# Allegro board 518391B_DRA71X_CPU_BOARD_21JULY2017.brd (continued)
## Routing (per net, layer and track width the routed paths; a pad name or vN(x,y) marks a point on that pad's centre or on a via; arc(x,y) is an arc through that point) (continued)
GND_EARTH: length 19.9
  TOP w0.508: J7.6 J7.8 J7.9 J7.7
VBAT: length 72.1
  TOP w0.635: J4.1 9.83,141.73 ; J4.1 6.68,141.73 ; J4.1 8.25,140.16 ; J4.1 8.25,143.31 ; J4.2 8.25,138.23 ; J4.2 9.83,136.65 ; J4.2 8.25,135.08 ; J4.2 6.68,136.65
  LY3 w0.508: 6.63,141.73 J4.1 ; J4.1 8.25,140.11 ; J4.1 9.88,141.73 ; J4.1 8.25,143.36 ; 6.63,136.65 J4.2 ; J4.2 8.25,135.03 ; J4.2 8.25,138.28 ; J4.2 9.88,136.65
  LY3 w0.635: 12,158.95 J22.1 ; J22.1 13.19,161.16 ; J22.1 10.81,161.16 ; J22.1 12,163.37
  LY4 w0.508: 8.25,140.11 J4.1 ; J4.1 9.88,141.73 ; J4.1 8.25,143.36 ; J4.1 6.63,141.73 ; J4.2 9.88,136.65 ; J4.2 8.25,135.03 ; J4.2 6.63,136.65 ; J4.2 8.25,138.28
  LY4 w0.635: J22.1 13.19,161.16 ; J22.1 10.81,161.16 ; J22.1 12,158.95 ; J22.1 12,163.37
  BOTTOM w0.254: v2(12.57,142.37) 14.99,139.95 22.73,139.95 23.62,140.84 U74.8 29.08,140.84 29.29,141.05 29.29,141.54 28.98,141.84 U74.10
VBAT_A: length 25.2
  TOP w0.406: C117.2 35.31,76.83 34.73,77.41 U28.3
  TOP w0.508: 44.45,139.78 TP5.1 ; TP5.1 44.45,141.15 ; TP5.1 43.76,140.46 ; TP5.1 45.14,140.46 ; L4.2 41.64,136.52 ; L4.2 38.37,136.52 ; L4.2 40,138.16
  LY3 w0.635: C65.1 36.32,113.46 ; C65.1 37.64,112.14 ; C65.1 35,112.14 ; C65.1 36.32,110.82 ; 43.76,140.46 TP5.1 ; TP5.1 44.45,139.78 ; TP5.1 45.14,140.46 ; TP5.1 44.45,141.15 ; L4.2 40,138.16 ; L4.2 41.64,136.52 ; L4.2 38.37,136.52 ; L4.2 40,134.89
  vias: v2(25.15,93.6) v2(25.15,92.71) v2(25.15,84.96) v2(25.15,84.07) v2(25.15,76.71) v2(25.15,75.82) v2(26.03,93.6) v2(26.03,92.71) v2(26.03,84.96) v2(26.03,84.07) v2(26.03,76.71) v2(26.03,75.82) v2(30.23,77.34) v2(30.23,76.45) v2(31.11,77.34) v2(31.11,76.45) v2(35.94,141.48) v2(35.94,140.46) v2(35.94,139.45) v2(35.94,138.43) v2(37.08,141.48) v2(38.23,141.48) v2(39.37,141.48) v2(40.51,141.48) v2(41.66,141.48) v2(42.8,141.48)
VBAT_F: length 5
  TOP w0.305: R45.1 44.7,111 44.15,110.44 D9.2 ; 42.87,108.71 TP15.1 ; TP15.1 43.56,109.4 ; TP15.1 43.56,108.03 ; TP15.1 44.25,108.71
  vias: v2(43.69,135) v2(43.69,134.11) v2(43.69,133.22) v2(43.69,132.33) v2(47.12,132.33) v2(48.01,132.33) v2(48.89,132.33) v2(49.78,132.33)
VBAT_PM: length 19.1
  TOP w0.508: 16.01,131.49 U16.4 17.21,131 ; C24.1 16.76,143.12 ; C24.1 16.01,142.24 ; C24.1 16.76,141.36
  BOTTOM w0.254: U74.9 23.23,141.34 22.35,140.46 16.38,140.46 v2(14.48,142.37)
  vias: v2(12.7,148.59) v2(12.7,147.7) v2(12.7,146.81) v2(12.7,145.92) v2(12.7,145.03) v2(13.59,149.1) v2(13.59,144.53) v2(14.61,149.1) v2(14.61,144.53) v2(15.62,149.1) v2(15.62,144.53)
VBAT_SYS: length 305.4
  TOP w0.203: U18.15 v2(79.62,127.88)
  TOP w0.305: v2(79.76,130.05) 80.26,130.05 80.7,129.62 C29.1 80.7,129.46 80.26,129.03 v2(79.76,129.03)
  TOP w0.635: 73.41,137.87 C23.1 ; C23.1 72.08,139.19 ; C23.1 74.73,139.19 ; C23.1 73.41,140.51 ; C2.1 50.16,158.29 ; C2.1 50.16,155.65 ; C2.1 48.84,156.97 ; C2.1 51.49,156.97 ; 67.94,155.65 C3.1 ; C3.1 66.62,156.97 ; C3.1 67.94,158.29 ; C3.1 69.27,156.97 ; 32.38,155.65 C1.1 ; C1.1 32.38,158.29 ; C1.1 33.71,156.97 ; C1.1 31.06,156.97 ; TP1.1 23.55,160.27 ; TP1.1 22.86,160.96 ; TP1.1 22.86,159.59 ; TP1.1 22.17,160.27
  LY4 w0.305: v2(79.76,129.03) 79.62,128.9 v2(79.62,127.88)
  LY4 w0.508: v2(108.33,21.72) 106.81,23.24 89.66,23.24 89.41,23.49 78.87,23.49 77.98,22.61 52.7,22.61 50.67,24.64 48.89,24.64 48.41,25.12 43.28,25.12 40.13,21.97 37.46,21.97 36.19,23.24 26.03,23.24 24.26,25.02 24.26,29.84 19.28,34.82 19.28,54.33 20.45,55.5 20.45,60.83 19.56,61.72 19.56,93.22 22.48,96.14 22.48,102.62 35.05,115.19 68.07,115.19 v2(69.85,116.97) 72.01,119.13 v2(72.01,122.3) 72.26,122.55 v2(72.26,124.08)
  BOTTOM w0.508: v2(72.01,122.3) 72.01,122.17 71.75,121.92 C552.1 71.75,120.01 72.01,119.76 ; 69.85,115.57 v2(69.85,116.97) ; R218.2 72.39,124.21 v2(72.26,124.08)
  BOTTOM w0.635: C1.1 34.54,156.97 ; C1.1 30.23,156.97 ; C1.1 32.38,159.13 ; C1.1 32.38,154.81 ; C2.1 52.32,156.97 ; C2.1 50.16,154.81 ; C2.1 50.16,159.13 ; C2.1 48.01,156.97 ; C23.1 73.41,141.35 ; C23.1 75.57,139.19 ; C23.1 71.25,139.19 ; C23.1 73.41,137.03 ; C3.1 70.1,156.97 ; C3.1 67.94,159.13 ; C3.1 65.79,156.97 ; C3.1 67.94,154.81 ; TP1.1 22.86,160.96 ; TP1.1 22.17,160.27 ; TP1.1 22.86,159.59 ; TP1.1 23.55,160.27
  vias: v2(17.91,160.15) v2(18.03,156.34) v2(18.8,160.15) v2(19.56,156.34) v2(19.69,160.15) v2(20.57,160.15) v2(20.95,156.34) v2(22.35,157.73) v2(86.61,128.4) v2(86.61,127.51) v2(87.38,128.4) v2(87.38,127.51) v2(88.14,128.4) v2(88.14,127.51)
VBUS1_5V0: length 3.2
  TOP w0.305: v2(128.65,154.31) R1.1
  BOTTOM w0.305: J1.1 136.01,160.52 ; J1.1 135.2,161.33 ; J1.1 134.39,160.52
  vias: v2(123.19,156.97) v2(123.19,156.08) v2(123.57,155.07) v2(123.57,154.05) v2(123.57,152.78) v2(123.57,151.64)
VBUS2_5V0: length 6.8
  TOP w0.305: 157.07,160.52 J2.1 ; J2.1 157.81,159.78 ; J2.1 157.81,161.25 ; J2.1 158.54,160.52
  BOTTOM w0.305: R194.1 155.96,154.31 v2(156.08,154.18)
VCC_APL: length 13.7
  LY3 w0.305: v2(92.08,161.93) 89.92,161.93 87.5,164.34 87.5,165.35 J3.5
  BOTTOM w0.254: J3.5 86.35,166.51 U1.8
  BOTTOM w0.305: v2(92.08,161.93) 92.08,162.81 93.22,162.81
VCC_LM5141: length 7.7
  TOP w0.305: D5.2 87.3,125.27 86.31,124.28 C45.1 84.12,124.28 83.19,125.22 U18.10
VCC_LM5175: length 24.1
  TOP w0.203: v2(47.62,110.49) 47.62,110.24 R48.2
  TOP w0.305: D6.2 52.25,123.62 v2(52.2,123.57) ; D8.2 49.61,123.57 C42.1 v2(52.2,123.57) ; v2(52.2,123.57) 51.98,123.36 U19.23
  BOTTOM w0.305: v2(52.2,123.57) 52.2,120.52 50.29,118.62 50.29,113.92 47.62,111.25 v2(47.62,110.49)
VDD33_DSU921: length 7.2
  TOP w0.305: U30.22 v2(145.01,68.04) 145.92,68.96 145.92,70.23 C122.1 L17.1
  BOTTOM w0.305: v2(145.01,68.04) 144.78,67.82 C429.1
VDD_1P1_CSI: length 3.4
  TOP w0.305: U33.20 147.84,51.32 v2(147.83,51.31)
  BOTTOM w0.305: v2(147.83,51.31) 148.08,51.56 C479.1 148.59,51.05 148.84,50.8 C485.2
VDD_1P1_D: length 4.3
  TOP w0.305: C142.1 C134.2 154.31,57.4 154.47,57.24 154.47,56.46 154.15,56.14 U33.3
VDD_1P1_FPD: length 4.2
  TOP w0.305: C171.1 C172.2 153.67,47.37 154.15,47.85 U33.34
VDD_1P8: length 5.6
  TOP w0.305: v2(155.18,47.47) 155.15,47.5 U33.36 ; C135.2 v2(157.23,57.28) ; L19.1 v2(159,57.28) ; v2(156.97,53.47) 156.82,53.32 U33.45
  BOTTOM w0.305: v2(155.18,47.47) 154.94,47.71 C486.1 ; v2(156.97,53.47) C471.1
VDD_1P8_CSI: length 5.3
  TOP w0.305: U33.17 147.97,52.82 v2(147.7,53.09)
  BOTTOM w0.305: L59.1 C468.2 148.59,53.72 C472.1 148.58,52.82 147.97,52.82 v2(147.7,53.09)
VDD_1P8_FPD: length 6.6
  TOP w0.305: v2(152.64,47.48) 152.65,47.49 U33.31 ; L24.1 C167.1 v2(157.1,47.75) ; v2(157.02,50.83) 156.97,50.83 156.96,50.82 U33.40
  BOTTOM w0.305: v2(152.64,47.48) 152.91,47.74 C487.1 ; C480.1 156.86,50.67 v2(157.02,50.83)
VDD_1V8_SW: length 1.4
  TOP w0.279: 80.26,55.88 80.27,55.89 U32.19
VDD_CORE_AVS: length 113.4
  TOP w0.102: 94.06,88.29 94.45,88.29 ; v1(91.34,88.28) 91.27,88.29 91.87,88.29 ; 90.57,81.78 90.16,81.78 90.15,81.77 ; 92.77,88.29 93.15,88.29 ; 90.55,88.28 90.16,88.28
  TOP w0.203: U27.N11 U27.P10 ; U27.R10 U27.T9 ; 93.15,88.29 v1(93.29,88.28) ; U27.J16 90.69,81.78 90.57,81.78 ; U27.V14 91.99,88.29 91.87,88.29 ; U27.N15 U27.P14 ; U27.M17 U27.N18 ; 90.55,88.28 90.69,88.28 U27.V16 ; v1(92.64,88.28) 92.77,88.29 ; 94.06,88.29 93.94,88.29 U27.V12 ; 90.16,88.28 90.04,88.28 U27.V18 ; U27.N13 U27.P12 ; U27.V10 95.56,87.31 U27.U9 ; U27.L12 U27.M11 ; U27.J18 90.15,81.77 ; 91.46,88.29 v1(91.34,88.28) ; v1(94.59,88.28) 94.45,88.29 94.45,88.29 ; 93.61,86.01 U27.R12 ; U27.K18 U27.L17
  TOP w0.254: U27.U9 v1(95.89,86.98) U27.T9 ; U27.U13 v1(93.29,86.98) U27.T13 ; U27.P16 U27.R17 U27.P18 ; U27.V10 v1(94.59,88.28) U27.W10 ; U27.T13 U27.R14 U27.T15 ; U27.T13 U27.R12 U27.T11 ; U27.T11 94.27,86.66 U27.R10 ; U27.T11 v1(94.59,86.98) U27.U11 ; U27.T15 91.66,86.66 U27.R16 v1(90.69,86.33) ; U27.T15 v1(91.99,86.98) U27.U15 ; U27.W12 v1(93.29,88.28) U27.V12 ; U27.V14 v1(92.64,88.28) U27.W14 ; 93.61,86.01 93.94,85.68 v1(93.94,85.68) ; U27.K18 v1(89.39,82.43) U27.J18 ; U27.U18 89.97,87.59 v1(90.04,87.63) U27.V18 ; U27.W16 v1(91.34,88.28) U27.V16
  TOP w0.305: U27.M13 v1(93.29,84.38) U27.N13 ; U27.N11 v1(94.59,84.38) U27.M11 ; U27.P14 v1(92.64,85.68) U27.R14 ; U27.M17 v1(90.69,83.73) U27.L17 ; U27.J15 91.34,82.35 U27.J16 ; v2(86.74,50.04) 86.87,50.16 86.87,51.31 86.47,51.71 U32.33 ; v1(91.34,85.68) U27.R16 ; U27.P18 v1(89.39,85.03) U27.N18 ; U27.R17 v1(90.69,86.33) U27.T17 ; U27.M15 v1(91.99,84.38) U27.N15 ; U27.R10 v1(95.24,85.68) U27.P10 ; U27.P12 v1(93.94,85.68) ; v1(93.94,83.08) U27.K12
  LY5_PWR w0.102: 96.01,83.06 96.27,82.8 100.08,82.8 101.35,81.53 101.35,79.76 104.14,76.96 104.14,74.6 104.34,74.4 104.34,74.08 104.14,73.88 104.14,72.64 103.66,72.16 103.66,70.26 103.12,69.72 103.12,68.58 102.23,67.69 99.69,67.69 99.44,67.44 97.16,67.44 96.77,67.06 95.25,67.06 95.1,66.9 94.39,66.9 94.11,67.18 92.71,67.18 92.33,66.8 92.33,63.75 91.82,63.25 91.82,62.74 92.33,62.23 92.33,53.47 90.93,52.07 89.92,52.07 88.52,50.67 87.38,50.67 v2(86.74,50.04)
  BOTTOM w0.254: C321.1 v1(93.29,88.28) ; C341.1 v1(91.99,84.38) ; 94.11,86.36 v1(93.94,85.68) ; v1(93.94,83.08) 94.11,83.31 94.34,83.54 94.36,83.54 C347.1
  BOTTOM w0.381: C344.1 107.44,84.7 107.06,85.08 v2(107.06,85.29) ; v4(109.09,82.7) C373.1 v4(106.62,82.7) ; v1(93.29,84.38) 93.29,84.37 C348.1 ; v2(106.59,90.25) C303.1 v2(109.15,90.25) ; C347.1 94.59,84.38 v1(94.59,84.38)
  BOTTOM w0.406: v2(105.84,93.04) C551.1 v2(103.45,93.04) ; C344.1 108.18,84.7 108.59,85.11 v2(108.59,85.29) ; v2(108.71,86.66) 108.65,86.6 C323.1 v2(106.05,86.6)
  vias: v2(86.78,42.92) v2(87.36,43.53) v2(87.88,42.93) v2(88.39,43.56) v2(88.9,42.93) v2(89.41,43.81) v2(90.26,42.87) v2(90.92,43.53) v2(91.4,42.92) v2(92.01,43.56) v2(92.6,42.87)
VDD_DDR_1V35: length 159.3
  TOP w0.254: U27.W17 v1(90.04,88.93) 89.71,88.61 U27.W18 ; v2(50.67,86.99) C89.1 v2(48.26,86.99) ; U27.V20 v1(88.09,88.28) U27.W20 ; U32.28 83.97,51.71 v2(83.57,51.31) ; U27.T20 v1(88.74,86.98) U27.T19 ; v2(48.45,79.74) C98.1 v2(50.86,79.74)
  TOP w0.305: U23.K8 v4(56.95,92.2) ; U29.N1 v4(54.55,84.37) ; U29.H9 v4(59.35,77.17) ; U29.K2 v4(56.95,83.57) ; U29.K8 v4(56.95,77.97) ; U29.F1 v4(60.95,84.37) ; U23.F1 v4(60.95,98.6) ; U29.C9 v4(63.35,77.17) ; U23.N1 v4(54.55,98.6) ; U23.B2 v4(64.15,97.8) ; U29.G7 v4(60.15,78.77) ; v2(66.98,80.7) C96.1 v2(68.28,80.67) ; U23.K2 v4(56.95,97.8) ; U23.N9 v4(54.55,91.4) ; U29.B2 v4(64.15,83.57) ; U23.C1 v4(63.35,98.6) ; U29.D2 v4(62.55,83.57) ; U23.E9 v4(61.75,91.4) ; C80.2 55.56,103.19 v2(54.23,101.85) ; U23.R1 v4(52.95,98.6) ; U23.R9 v4(52.95,91.4) ; U29.A1 v4(64.95,84.37) ; v2(50.37,94.41) C84.1 v2(48.95,94.41) ; U29.E9 v4(61.75,77.17) ; U23.C9 v4(63.35,91.4) ; U23.G7 v4(60.15,93) ; U29.R1 v4(52.95,84.37) ; U29.H2 v4(59.35,83.57) ; U23.A1 v4(64.95,98.6) ; U23.A8 v4(64.95,92.2) ; U29.R9 v4(52.95,77.17) ; U23.D2 v4(62.55,97.8) ; U29.C1 v4(63.35,84.37) ; U29.A8 v4(64.95,77.97) ; U23.D9 v4(62.55,91.4) ; U29.N9 v4(54.55,77.17) ; U23.H9 v4(59.35,91.4) ; U29.D9 v4(62.55,77.17) ; U23.H2 v4(59.35,97.8)
  LY3 w0.254: v2(83.57,51.31) 83.57,47.37 v2(84.2,46.74)
  LY5_PWR w0.102: v2(84.2,46.74) 77.22,53.72 68.71,53.72 67.54,54.89 66.96,54.89 66.65,55.2 66.65,59.21 66.29,59.56 66.29,60.07 66.67,60.45 66.67,70.23 66.93,70.48 66.93,70.87 66.55,71.25 66.55,74.8 69.37,77.62 75.98,77.62 76.16,77.44 77.19,77.44 82.42,82.68 84.96,82.68 85.6,83.31 85.6,84.58 85.85,84.84 88.27,84.84 88.77,85.34 88.77,85.98
  BOTTOM w0.254: v1(88.09,88.28) 87.95,88.42 C315.1 ; v4(77.93,90.03) C311.1 v4(77.93,88.67) ; v4(82.27,94.14) 81.86,93.72 C294.1 81.74,93.51 v4(81.4,93.17) ; v4(83.31,93.35) 83.44,93.22 C297.1 v4(84.2,92.71) ; C319.1 v1(90.04,88.93) ; v4(76.15,89.99) C312.1 v4(76.15,88.65) ; C336.1 v4(64.95,84.37) ; v4(83.68,95.01) 83.24,94.57 C293.1 83.24,94.26 v4(82.88,93.9) ; C307.1 73.13,90.47 73.43,90.17 ; C300.1 v4(64.95,92.2) ; 54.48,99.31 v4(54.55,98.6) ; C279.1 v4(60.95,98.6) ; v4(80.9,93.6) 80.49,93.19 C295.1 80.02,92.86 v4(79.78,92.86) ; C305.1 v4(59.35,91.4) ; C383.1 v4(59.35,77.17) ; C337.1 v4(60.95,84.37) ; C378.1 v4(64.95,77.97) ; C278.1 v4(64.95,98.6) ; 54.48,85.09 v4(54.55,84.37) ; C304.1 v4(63.35,91.4) ; C382.1 v4(63.35,77.17)
  BOTTOM w0.305: v2(63.27,75.51) C391.1 v2(63.22,74.09) ; v2(54.23,101.85) 54.48,100.97 v2(54.23,100.08) ; v2(63.27,88.32) C313.1 v2(63.25,89.74) ; v2(60.81,100.05) C273.1 v2(60.86,101.85) ; v2(52.07,74.55) C386.2 v2(52.07,76.45) ; C325.1 88.76,86.96 v1(88.74,86.98) ; v2(64.08,100.05) C272.1 v2(64.06,101.85) ; v2(58.99,75.69) C392.1 v2(59.05,74.14) ; v2(60.58,85.85) C327.1 v2(61.09,87.63) ; v2(64.06,85.9) C326.1 v2(64.13,87.58) ; v2(59.26,88.32) C314.1 v2(59.23,89.74) ; C299.1 v2(66.48,92.58) ; v2(54.23,87.63) 54.48,86.74 v2(54.23,85.85) ; v2(66.48,78.36) C377.1
  BOTTOM w0.381: v4(70.18,84.12) C352.1 v4(70.18,82.8) ; v4(74.07,90.17) 73.43,90.17 ; v4(73.81,84.09) C354.1 v4(73.81,82.79) ; C307.1 72.9,90.62 72.9,91.31 v4(73.03,91.44) ; v4(71.96,82.8) C351.1 v4(71.96,84.11)
  BOTTOM w0.406: v4(82.68,96.79) C289.1 v4(85.14,96.79)
  vias: v2(48.13,66.17) v2(50.42,66.17) v2(51.43,66.17) v2(53.21,66.17) v2(56.13,66.29) v2(57.53,66.29) v2(58.8,66.29) v2(61.21,66.29) v2(62.61,66.29) v2(63.37,59.18) v2(63.37,58.17) v2(63.37,57.15) v2(63.37,56.13) v2(63.5,60.71) v2(63.63,52.07) v2(64.13,66.29) v2(64.39,60.71) v2(65.28,60.71) v2(77.51,42.87) v2(78.09,43.48) v2(78.73,42.84) v2(79.29,43.48) v2(79.77,42.87) v2(80.45,43.48) v2(80.99,42.82) v2(81.65,43.48) v2(82.13,42.87) v2(82.74,43.51) v2(83.32,42.82)
VDD_DSP_AVS: length 67.4
  TOP w0.102: 93.82,81.14 93.41,81.14 93.4,81.14 ; 95.89,81.13 v1(95.89,80.48) ; 95.12,81.13 94.71,81.13 ; 93.41,82.43 93.82,82.43 ; 93.94,81.14 93.94,81.13 v1(93.94,80.48)
  TOP w0.203: 93.82,82.43 93.94,82.43 ; 94.71,81.13 94.59,81.13 ; 95.24,81.13 95.12,81.13 ; 93.28,81.14 93.4,81.14 ; 93.41,82.43 93.29,82.43 93.27,82.42 ; 93.82,81.14 93.94,81.14
  TOP w0.279: U32.9 83.97,61.19
  TOP w0.305: U27.H9 95.24,81.13 ; U27.H9 95.89,81.13 ; U27.H9 v1(95.89,81.78) U27.J9 ; 93.27,82.42 92.96,82.11 U27.J13 ; U27.H13 93.29,81.78 v1(93.29,81.78) U27.J13 ; U27.H13 93.28,81.14 ; U27.H13 v1(92.64,81.78) 92.96,82.11 U27.J13 ; U27.H11 93.94,81.14 ; U27.H11 94.26,81.46 v1(94.59,81.78) U27.J11 93.94,82.43 ; U27.H11 94.59,81.13 ; 83.97,61.19 83.95,61.21 v2(83.95,67.06)
  LY5_PWR w0.102: v2(83.95,67.06) 84.45,67.56 88.52,67.56 88.65,67.44 89.53,67.44 89.66,67.56 94.11,67.56 94.61,68.07 98.3,68.07 98.55,67.82 99.19,67.82 99.44,68.07 101.98,68.07 102.74,68.83 102.74,71.75 103.76,72.77 103.76,73.9 103.58,74.08 103.58,74.4 103.76,74.58 103.76,76.83 100.97,79.63 100.97,81.15 100.84,81.28 100.46,81.28
  BOTTOM w0.254: v4(97.69,73.66) 97.7,73.65 C403.1 v4(97.7,71.12) ; v4(103.23,73.6) C393.1 101.49,75.33 v4(101.49,75.33) ; v1(93.29,81.78) C361.1 ; C362.1 v1(94.59,81.78)
  BOTTOM w0.305: C357.1 96.35,82.24 96.08,81.97 v1(95.89,81.78) ; C370.1 v1(95.89,80.48)
  BOTTOM w0.381: v4(83.74,76.75) 83.71,76.75 82.84,75.89 81.89,74.96 v4(81.89,74.96)
  BOTTOM w0.406: v4(95.56,71.21) C402.1 v4(95.56,73.66) ; v4(92.02,73.66) C401.1 v4(92.02,71.22)
  vias: v2(77.08,69.44) v2(77.66,68.75) v2(78.27,69.39) v2(78.75,68.78) v2(79.41,69.44) v2(79.95,68.78) v2(80.63,69.39) v2(81.11,68.78) v2(81.67,69.41) v2(82.31,68.78) v2(82.89,69.39)
VDD_DSP_SW: length 2.2
  TOP w0.279: 83.24,61.75 82.97,61.48 U32.11
VDDA_LM5141: length 12.1
  TOP w0.203: v2(81.91,119.25) R35.2 R34.2 ; C53.1 v2(78.36,121.86) 78.36,121.92 78.63,122.19 U18.2
  BOTTOM w0.305: R221.2 77.79,121.28 v2(78.36,121.86) 78.74,121.48 78.74,119.38 79.5,118.62 81.28,118.62 v2(81.91,119.25)
VDDI_MMC2: length 2.7
  TOP w0.305: U31.E4 v2(122.2,70.42)
  BOTTOM w0.305: C436.1 122.14,70.48 v2(122.2,70.42) 122.81,71.02 C433.1
VDDIO_DSU921: length 5.3
  TOP w0.305: L16.2 C116.1 140.84,71.6 140.83,71.58 140.83,70.78 v2(140.85,70.76) 140.84,70.76 U30.30
  BOTTOM w0.305: v2(140.85,70.76) 140.85,70.23 C409.1
VDDR_VREFSTL: length 136.1
  TOP w0.254: C91.1 v2(59.49,86.99) ; 60.33,48.13 v4(61.21,48.13) ; U29.M8 v4(55.35,77.97) ; U27.Y20 v1(88.09,89.58)
  TOP w0.305: U29.H1 v4(59.35,84.37) ; U35.6 61.26,48.18 v4(61.21,48.13) ; v2(56.01,88.31) 58.23,88.31 58.74,87.8 C91.1 ; U23.M8 v4(55.35,92.2) ; U23.H1 v4(59.35,98.6)
  TOP w0.381: C80.1 C82.1 59.35,100.67 v4(59.35,98.6)
  TOP w0.508: v4(57.78,76.96) 57.78,74.68 57.02,73.91 54.23,73.91 v2(53.59,74.55) 52.83,73.79 48.26,73.79 47.12,72.64 v2(47.12,65.15)
  LY3 w0.381: v4(55.35,92.2) 55.41,92.2 56.01,91.59 56.01,88.31 v2(56.01,88.31)
  LY3 w0.508: v2(47.12,65.15) 49.02,63.25 54.86,63.25 v2(57.53,60.58)
  LY4 w0.381: v1(88.09,89.58) 88.09,89.36 87.76,89.03 86.87,89.03 86.61,89.28 84.96,89.28 83.68,90.56 83.68,92.93 84.07,93.32 84.07,93.6 80.64,97.03 80.52,97.03 78.97,98.58 66.14,98.58 65.6,99.12 59.87,99.12 v4(59.35,98.6)
  BOTTOM w0.305: C386.1 v2(53.59,74.55)
  BOTTOM w0.381: v4(55.35,77.97) 55.38,77.97 56.72,76.63 57.45,76.63 v4(57.78,76.96) 58.66,77.84 58.66,83.68 v4(59.35,84.37) 59.35,85.51 59.54,85.7 59.54,86.94 v2(59.49,86.99) 58.53,87.95 58.53,91.04 58.83,91.34 58.83,93.21 59.13,93.52 62.38,93.52 62.76,93.9 62.76,96.06 62.35,96.48 59.13,96.48 58.83,96.78 58.83,98.01 59.16,98.34 59.16,98.41 v4(59.35,98.6)
  BOTTOM w0.508: v2(57.53,60.58) 59.69,58.42 59.69,51.18 61.21,49.66 v4(61.21,48.13)
VDDS_1V8: length 161.1
  TOP w0.254: U27.U7 v1(96.54,86.98) U27.U8 ; U27.H20 v1(88.09,81.78) ; U27.Y18 v1(89.39,88.93) U27.Y19 v1(89.39,89.58) ; v1(89.39,90.23) U27.AA19 ; U27.F7 v1(97.19,80.48) U27.G7 97.01,80.95 97.01,81.31 U27.H7 ; U32.17 80.91,56.88 80.77,57.02 v2(79.88,57.02) ; U27.W7 v1(96.54,88.28) ; v1(88.09,85.68) U27.P20 ; U27.R7 v1(96.54,85.68) U27.P7 ; v1(94.59,80.48) 94.26,80.81 U27.G11
  TOP w0.305: U31.P3 v2(121.2,60.41) ; U26.2 149.1,86.97 149.1,85.72 v2(148.97,85.6) ; U31.L4 v2(122.2,63.41) ; U31.L9 v2(128.21,63.41) ; U31.L2 v2(120.2,63.41) ; U24.1 120.28,97.65 v2(120.27,97.66) 119.89,97.66 119.25,97.03 R59.1 ; L19.2 v2(159,60.58) ; R170.1 R171.1 v2(70.1,16) ; U31.P8 v2(127.21,60.41) ; U31.H3 v2(121.2,67.41) ; v2(159.26,44.32) 158.88,44.7 L24.2 ; v2(131.57,112.01) 131.72,112.17 132.56,112.17 Y1.4 ; v2(117.47,90.42) 117.45,90.45 U75.5 ; Q8.2 v2(84.84,40.51) ; U31.H8 v2(127.21,67.41) ; R127.2 v2(75.56,47.75) ; U31.L7 v2(126.21,63.41)
  TOP w0.381: v4(81.79,78.23) 81.64,78.08 C108.1 v4(79.53,78.08)
  TOP w0.508: v2(134.15,105.28) 134.16,105.28 C77.1 135.36,105.38 136.52,105.38 136.65,105.26 U21.34 ; RJ12.1 v2(63.18,37.85)
  LY3 w0.254: 96.54,87.5 v1(96.54,86.98) 96.54,86.98 96.54,85.77 v1(96.54,85.68)
  LY3 w0.305: v2(70.1,16) 70.1,16.89 67.82,19.18 67.82,36.58 v2(65.66,38.73)
  LY3 w0.381: 96.54,87.5 v1(96.54,88.28)
  LY3 w0.508: v2(134.15,105.28) 131.86,107.57 v2(121.79,107.57)
  LY4 w0.203: 91.93,81.15 92.33,81.15 92.59,80.89 94.18,80.89 v1(94.59,80.48)
  LY4 w0.254: v2(76.33,57.66) 76.96,57.02 v2(79.88,57.02)
  LY4 w0.305: v2(120.27,97.66) 119.51,96.9 119.51,92.46 v2(117.47,90.42)
  LY4 w0.508: v2(121.79,107.57) 120.27,106.04 v2(120.27,97.66)
  LY5_PWR w0.102: v2(76.33,57.66) 76.43,57.76 76.43,73.51 77.32,74.4 79.35,74.4 79.63,74.68 80.9,74.68 85.72,79.5 85.72,80.9 85.6,81.03 85.6,81.28
  BOTTOM w0.254: v1(89.39,88.93) 89.39,89.51 v1(89.39,89.58) v1(89.39,90.23) 89.39,91.81 C298.1 ; C318.1 v1(96.54,88.28)
  BOTTOM w0.305: v2(127.21,60.41) 127,60.2 C427.1 ; C550.1 v2(117.47,90.42) ; R296.2 122.93,64.13 v2(122.2,63.41) ; 119.38,62.48 119.38,62.59 v2(120.2,63.41) ; C271.1 131.7,111.89 v2(131.57,112.01) ; R246.1 R245.1 148.84,85.72 v2(148.97,85.6) ; R289.1 126.36,63.25 v2(126.21,63.41) ; P9.40 159.53,80.63 v2(159.77,80.39) ; v2(120.27,97.66) 120.4,97.54 C291.1 ; v2(127.21,67.41) 127,67.21 C411.1 ; R273.1 v2(121.16,65.41) R269.1 ; v2(147.45,56.45) 147.07,56.07 L59.2 ; R295.1 v2(125.22,61.47) ; v1(96.54,85.68) 96.62,85.76 C342.1 ; v2(128.21,63.41) 128.25,63.37 R268.1 R270.1 ; v2(125.98,59.18) 125.98,58.85 125.68,58.55 R300.1 ; R272.1 125.35,65.28 v2(125.22,65.41) ; P9.38 v2(160.02,81.13) ; v2(155.83,44.2) 155.83,44.96 154.69,44.96
  BOTTOM w0.381: C428.1 v2(75.31,68.2) ; C434.1 v2(75.31,66.8)
  vias: v2(71.48,60.73) v2(71.44,59.49) v2(71.49,58.36) v2(71.44,57.14) v2(71.49,56) v2(72.12,60.2) v2(72.1,58.85) v2(72.1,57.68) v2(72.1,56.48) v2(72.12,55.39) v2(95.76,47.5) v2(95.76,46.48) v2(96.9,47.5) v2(96.9,46.48) v2(155.19,72.64) v2(156.08,72.64)
3INP_A: length 5.8
  TOP w0.127: U28.11 34.23,82.49 34.8,81.91 v2(36.64,81.91) C103.1
  BOTTOM w0.127: R261.1 v2(36.64,81.91)
4INM_A: length 10
  TOP w0.203: U28.10 34.23,81.85 35.05,81.03 41.02,81.03 41.96,80.09 C110.1
4INP_A: length 6.2
  TOP w0.203: C109.1 v2(36.64,80.14) 36.39,80.39 35.05,80.39 34.23,81.22 U28.9
  BOTTOM w0.203: C381.1 v2(36.64,80.14)
APL_RSTN: length 146.8
  TOP w0.127: U27.H4 v1(99.14,81.78)
  LY3 w0.133: v2(120.4,77.47) 119.13,77.47 117.98,78.61 113.79,78.61 112.9,77.72 106.55,77.72 104.27,80.01 101.85,80.01 100.46,81.41 99.52,81.41 v1(99.14,81.78)
  LY4 w0.133: v2(90.8,164.59) 91.57,165.35 94.61,165.35 95.25,164.72 116.59,164.72 125.73,155.57 125.73,149.86 127.76,147.83 127.76,136.78 122.81,131.83 122.81,91.69 119.76,88.65 119.76,78.1 v2(120.4,77.47)
  BOTTOM w0.127: R190.1 v2(90.8,164.59)
APL_SCL: length 10.1
  LY3 w0.133: J3.1 82.04,168.27 84.07,168.27 84.58,167.77 84.58,165.99 v2(84.84,165.74)
  BOTTOM w0.127: U1.6 85.35,165.22 v2(84.84,165.74) ; R193.1 J3.1
APL_SDA: length 10.1
  LY3 w0.133: J3.3 83.31,165.61 85.85,163.07 v2(85.85,160.91)
  BOTTOM w0.127: R192.1 J3.3 ; U1.2 v2(85.85,160.91)
BT_EN: length 83.1
  TOP w0.127: U21.10 v2(148.84,121.4) ; U27.AA4 v1(99.14,90.23)
  LY3 w0.133: v2(133.99,96.39) 131.7,96.39 131.32,96.77 129.92,96.77 129.37,96.22 128.69,96.22 127.76,97.16 125.73,97.16 124.97,96.4 122.82,96.4 122.68,96.27 112.27,96.27 111.63,95.63 102.49,95.63 99.14,92.28 v1(99.14,90.23)
  LY4 w0.133: v2(133.99,96.39) 134.58,96.98 134.58,107.87 133.99,108.46 133.99,120.4 136.02,122.43 142.71,122.43 143.76,121.37 148.81,121.37 v2(148.84,121.4)
  BOTTOM w0.127: R224.2 148.59,121.16 v2(148.84,121.4)
CAM_D0: length 77.7
  TOP w0.127: v2(147.57,49.32) U33.24 ; v2(113.66,51.94) 113.69,51.96 J14.35 ; v1(95.89,77.88) 96.21,78.21 U27.C8
  LY3 w0.133: v2(113.66,51.94) 115.2,51.94 115.58,51.56 120.65,51.56 121.16,52.07 126.24,52.07 128.26,54.1 138.69,54.1 143.46,49.32 v2(147.57,49.32) ; v1(95.89,77.88) 95.89,76.45 98.35,73.99 98.35,72.98 102.36,68.96 102.36,59.31 104.65,57.02 104.65,56.64 v2(105.54,55.75)
  BOTTOM w0.127: v2(105.54,55.75) 106.05,55.24 111.76,55.24 113.66,53.34 v2(113.66,51.94)
CAM_D1: length 77.2
  TOP w0.102: U27.B9 95.89,77.24 95.89,76.17
  TOP w0.127: J14.37 v2(113.18,52.58) ; 95.89,76.17 95.89,75.44 97.27,74.05 97.27,73.33 97.46,73.14 98.18,73.14 99.57,71.75 99.57,70.74 102.74,67.56 102.74,56.64 103.47,55.92 v2(103.47,55.88) ; v2(146.94,49.82) U33.23
  LY3 w0.133: v2(146.94,49.82) 143.47,49.82 138.94,54.36 128.14,54.36 126.53,52.75 120.06,52.75 119.25,51.94 116.2,51.94 115.57,52.58 v2(113.18,52.58)
  BOTTOM w0.127: v2(113.18,52.58) 113.18,53.19 111.38,54.99 105.54,54.99 104.65,55.88 v2(103.47,55.88)
CAM_D2: length 76.9
  TOP w0.127: v2(147.57,50.29) 147.6,50.32 U33.22 ; J14.39 v2(112.68,51.94) ; v2(104.52,55.24) 104.52,59.31 103.76,60.07 103.76,67.69 100.33,71.12 100.33,72.3 96.86,75.77 U27.A7
  LY3 w0.133: v2(147.57,50.29) 143.51,50.29 139.06,54.74 127.89,54.74 126.22,53.07 124.76,53.07 123.02,53.06 123.01,53.06 122.99,53.06 122.99,53.06 112.88,53.06 112.68,52.87 v2(112.68,51.94)
  BOTTOM w0.127: v2(104.52,55.24) 105.16,54.61 111,54.61 112.68,52.92 v2(112.68,51.94)
CAM_D3: length 77
  TOP w0.127: v2(146.94,50.82) U33.21 ; U27.A9 95.56,75.2 96.27,74.5 96.27,73.3 96.69,72.89 97.57,72.89 98.93,71.53 98.93,70.99 102.36,67.56 102.36,56.01 v2(103.12,55.24) ; J14.41 v2(112.19,52.58)
  LY3 w0.133: v2(112.19,52.58) 112.27,52.66 112.27,53.09 112.5,53.32 122.88,53.32 122.88,53.32 122.91,53.32 122.91,53.32 124.66,53.32 124.66,53.33 125.97,53.33 127.76,55.12 140.21,55.12 144.51,50.82 v2(146.94,50.82)
  BOTTOM w0.127: v2(112.19,52.58) 112.19,52.91 110.74,54.36 104.65,54.36 103.76,55.24 v2(103.12,55.24)
CAM_D4: length 78.4
  TOP w0.127: U27.A8 96.21,75.7 99.82,72.09 99.82,70.84 103.12,67.54 103.12,58.8 103.89,58.04 103.89,54.86 v2(103.63,54.61) ; J14.43 v2(111.69,51.94) ; v2(146.94,51.82) U33.19
  LY3 w0.133: v2(146.94,51.82) 144.14,51.82 140.48,55.48 124.19,55.48 122.29,53.58 112.13,53.58 111.69,53.14 v2(111.69,51.94)
  BOTTOM w0.127: v2(111.69,51.94) 111.69,52.91 110.49,54.1 104.14,54.1 v2(103.63,54.61)
CAM_D5: length 79.5
  TOP w0.127: v2(147.57,52.32) U33.18 ; J14.45 v2(111.19,52.58) ; U27.A11 94.26,74.35 93.98,74.06 93.98,73.15 95.38,71.75 95.88,71.75 96.27,71.37 96.27,70.99 97.28,69.98 98.04,69.98 100.33,67.69 100.33,55.88 100.37,55.84 v2(100.37,55.37)
  LY3 w0.133: v2(111.19,52.58) 111.12,52.64 111.12,53.09 111.88,53.84 122.04,53.84 123.95,55.75 140.85,55.75 144.28,52.32 v2(147.57,52.32)
  BOTTOM w0.127: v2(100.37,55.37) 102.23,55.37 103.76,53.85 109.98,53.85 111.19,52.64 v2(111.19,52.58)
CAM_D6: length 83.1
  TOP w0.127: U33.16 148.23,53.32 147.95,53.59 147.32,53.59 v2(146.81,53.09) ; U27.F10 v1(94.59,79.83) ; J14.47 v2(110.69,51.94)
  LY3 w0.133: v2(146.81,53.09) 144.65,53.09 141.73,56.01 123.7,56.01 121.79,54.1 111.77,54.1 111.77,54.1 111.63,54.1 110.69,53.15 v2(110.69,51.94) ; v1(94.59,79.83) 94.61,79.81 94.61,79.81 94.61,77.22 94.86,76.97 94.86,75.19 96.14,73.91 96.14,73.53 98.17,71.5 98.17,70.74 101.22,67.69 101.22,56.13 101.98,55.37 v2(101.98,54.23)
  BOTTOM w0.127: v2(110.69,51.94) 110.11,51.94 108.97,53.09 103.5,53.09 102.36,54.23 v2(101.98,54.23)
CAM_D7: length 78.9
  TOP w0.127: U27.A10 94.91,74.5 95.12,74.3 95.12,73.28 96.14,72.26 97.27,72.26 98.25,71.29 98.25,70.92 101.35,67.82 101.35,59.14 101.22,59.01 101.22,56.13 101.47,55.88 v2(101.47,54.86) ; U33.15 148.36,53.82 148.21,53.97 146.43,53.97 v2(146.05,53.59) ; J14.49 v2(110.19,52.58)
  LY3 w0.133: v2(146.05,53.59) 144.78,53.59 142.11,56.26 141.85,56.26 141.84,56.27 123.45,56.27 121.66,54.48 111.25,54.48 110.11,53.34 110.11,52.65 v2(110.19,52.58)
  BOTTOM w0.127: v2(101.47,54.86) 102.23,54.86 103.63,53.47 109.3,53.47 v2(110.19,52.58)
CAM_D8: length 33.3
  TOP w0.102: U27.B10 95.24,77.23 95.24,76.17
  TOP w0.127: 95.24,76.17 95.24,75.06 96.01,74.29 96.01,73.13 96.49,72.64 96.57,72.64 96.58,72.63 97.37,72.63 98.6,71.4 98.6,70.94 101.9,67.64 v2(101.9,58.38) ; J14.51 v2(109.69,56.26)
  BOTTOM w0.127: v2(109.69,56.26) 107.91,58.04 103.25,58.04 102.91,58.38 v2(101.9,58.38)
CAM_D9: length 35.5
  TOP w0.127: U27.E10 v1(95.24,79.18) ; J14.53 v2(109.19,55.72)
  LY3 w0.133: v2(101.73,56.52) 101.73,57.31 101.48,57.56 101.48,68.57 97.28,72.77 97.28,73.91 95.25,75.95 95.25,77.22 94.85,77.62 94.85,78.8 v1(95.24,79.18)
  BOTTOM w0.127: v2(101.73,56.52) 101.85,56.39 108.52,56.39 v2(109.19,55.72)
CAM_DE0: length 38.2
  TOP w0.102: U27.B7 97.19,77.23 97.19,76.17
  TOP w0.127: J14.27 115.68,55.99 v2(116.2,56.52) ; 97.19,76.17 97.19,75.8 100.58,72.41 100.58,71.25 104.01,67.82 104.01,61.6 105.22,60.39 105.22,57.59 v2(106.93,55.88)
  LY4 w0.133: v2(116.2,56.52) 115.95,56.77 107.82,56.77 v2(106.93,55.88)
CAM_FLD0: length 37.5
  TOP w0.127: v2(115.06,68.45) 115.57,67.94 115.57,64.77 115.18,64.38 J14.29 ; U27.C7 v1(97.19,77.88)
  LY3 w0.133: v2(115.06,68.45) 106.17,68.45 103.12,71.5 102.49,71.5 97.19,76.8 v1(97.19,77.88)
CAM_HSYNC: length 77.6
  TOP w0.127: v1(95.89,79.18) U27.E8 ; J14.31 114.69,56.26 v2(114.68,56.26) 114.69,56.27 114.69,64.65 115.02,64.99 v2(115.02,67.44) ; v2(150.24,56.56) 150.24,56.52 150.65,56.11 U33.10
  LY3 w0.133: v2(114.68,56.26) 115.7,55.24 121.68,55.24 123.32,56.89 144.65,56.89 145.03,57.27 149.53,57.27 v2(150.24,56.56) ; v2(115.02,67.44) 105.03,67.44 98.87,73.6 98.87,74.23 96.52,76.58 96.52,78.55 v1(95.89,79.18)
CAM_PCLK: length 74.4
  TOP w0.127: J14.25 v2(116.18,55.73) ; U27.D8 v1(95.89,78.53)
  LY3 w0.133: v2(148.59,57.69) 148.55,57.66 144.4,57.66 143.89,57.15 116.97,57.15 116.71,56.89 116.71,56.26 v2(116.18,55.73) ; v2(104.39,60.2) 102.74,61.85 102.74,69.09 98.61,73.22 98.61,74.11 96.27,76.45 96.27,78.16 v1(95.89,78.53)
  BOTTOM w0.127: R305.1 150.69,58.76 149.58,57.66 148.63,57.66 v2(148.59,57.69) ; v2(104.39,60.2) 105.79,58.8 108.71,58.8 110.36,57.15 114.77,57.15 v2(116.18,55.73)
CAM_VSYNC: length 74.7
  TOP w0.102: U27.B8 96.54,77.24 96.54,76.17
  TOP w0.127: v2(103.89,59.05) 103.5,59.44 103.5,67.56 100.08,70.99 100.08,72.2 96.54,75.74 96.54,76.17 ; J14.33 114.19,55.6 v2(114.05,55.74) ; U33.9 151.15,56.47 v2(151.09,56.53)
  LY3 w0.133: v2(114.05,55.74) 115.05,54.74 121.54,54.74 123.43,56.63 144.75,56.63 144.77,56.64 144.78,56.64 145.15,57.01 148.98,57.01 149.86,56.13 150.7,56.13 v2(151.09,56.53)
  BOTTOM w0.127: v2(114.05,55.74) 111.14,55.74 108.46,58.42 104.52,58.42 v2(103.89,59.05)
CAMERA_LOCK: length 82
  TOP w0.127: U33.48 v2(155.93,55.63) ; U27.L6 v1(97.19,83.73)
  LY3 w0.133: v1(97.19,83.73) 98.12,82.81 100.45,82.81 102.11,81.15 104.78,81.15 106.43,79.5 113.16,79.5 113.41,79.76 116.97,79.76 TP31.1 119.51,78.74 120.78,78.74 122.54,76.97 127.62,76.97 128.35,76.25 131.24,76.25 131.58,76.59 136.28,76.59 137.03,77.34 146.81,77.34 147.7,76.45 v2(149.35,76.45)
  LY4 w0.133: v2(155.93,55.63) 155.93,56.36 156.21,56.64 156.21,57.78 151.76,62.23 151.76,71.75 149.35,74.17 v2(149.35,76.45)
CAMERA_PDB: length 93.1
  TOP w0.127: U33.30 152.15,47.12 v2(151.76,46.74) 151.64,46.61 C173.1 ; U27.L5 v1(98.49,83.73)
  LY3 w0.133: v1(98.49,83.73) 99.11,83.12 100.53,83.12 102.06,81.58 104.85,81.58 105.9,80.53 112.51,80.53 112.9,80.14 116.33,80.14 117.31,81.12 118.14,81.12 120.14,79.12 121.03,79.12 122.92,77.24 124.73,77.24 124.93,77.43 136.36,77.43 136.53,77.6 147.3,77.6 147.69,77.22 v2(148.59,77.22)
  LY4 w0.133: v2(151.76,46.74) 148.97,46.74 148.21,47.5 148.21,51.09 148.25,51.13 148.25,51.48 148.21,51.52 148.21,56.52 149.86,58.17 149.86,69.6 148.59,70.87 v2(148.59,77.22)
  BOTTOM w0.127: 150.88,46.74 v2(151.76,46.74)
CANH_1: length 11.2
  TOP w0.127: v2(131.32,25.65) 128.27,25.65 127.38,26.54 R151.1 127.38,29.97
  BOTTOM w0.127: v2(131.32,25.65) 131.7,25.27 R393.1 132.84,23.62 J17.4
CANH_2: length 10
  TOP w0.127: U45.7 v2(135,28.45)
  BOTTOM w0.127: v2(135,28.45) R388.1 135,25.78 134.49,25.27 R393.2 133.86,24.51 133.72,24.37 133.72,23.12 132.74,22.14 J17.12
CANL_1: length 9.9
  TOP w0.127: U46.6 v2(126.11,28.45)
  BOTTOM w0.127: v2(126.11,28.45) R389.2 127.38,25.78 130.05,25.78 R394.1 130.68,23.57 J17.3
CANL_2: length 13.8
  TOP w0.127: U45.6 R152.2 131.83,25.15 v2(128.78,25.15)
  BOTTOM w0.127: J17.11 129.67,22.38 R394.2 v2(128.78,25.15)
CLK1X_A: length 94.1
  TOP w0.127: C76.1 v2(48.39,105.54) ; R57.2 v2(126.49,92.84)
  LY3 w0.133: v2(125.6,103.12) 119.51,103.12 116.59,106.04 100.08,106.04 v2(96.77,109.35)
  LY4 w0.133: v2(96.77,109.35) 84.33,109.35 83.44,108.46 51.31,108.46 v2(48.39,105.54) ; v2(126.49,92.84) 125.86,93.47 125.86,94.11 126.24,94.49 126.24,95 125.6,95.63 v2(125.6,103.12)
CLK2X_B: length 85.6
  TOP w0.127: v2(77.69,122.3) 76.33,120.94 R39.2
  TOP w0.203: v2(77.69,122.3) 77.72,122.3 78.13,122.71 U18.1
  LY3 w0.133: v2(123.32,122.81) 101.22,122.81 96.65,118.24 79.76,118.24 77.69,120.31 v2(77.69,122.3)
  LY4 w0.133: v2(123.32,96.9) v2(123.32,122.81)
  BOTTOM w0.127: R427.2 121.92,94.49 122.81,95.38 122.81,96.39 v2(123.32,96.9)
  BOTTOM w0.203: R221.1 v2(77.69,122.3)
CLK8X_A: length 169.1
  TOP w0.127: RJ9.1 v2(41.91,87.25) ; R58.2 129.54,93.09 v2(129.92,93.09) ; RJ2.1 v2(96.14,135.64)
  LY3 w0.133: v2(75.06,112.78) 76.83,114.55 76.83,122.55 77.22,122.94 77.22,128.65 81.79,133.22 91.19,133.22 93.6,135.64 v2(96.14,135.64) 97.92,135.64 101.85,131.7 v2(130.18,131.7)
  LY4 w0.133: v2(75.06,112.78) 73.91,112.78 70.86,109.72 49.02,109.72 43.43,104.14 43.43,88.77 v2(41.91,87.25) ; v2(129.92,93.09) 129.54,93.47 129.54,96.9 128.78,97.66 128.78,123.7 130.18,125.09 v2(130.18,131.7)
CLK8X_A_10V5: length 127.3
  TOP w0.127: RJ15.3 v2(157.99,12.19) ; R60.2 v2(129.92,92.33)
  LY3 w0.133: v2(161.74,95) 161.42,95 161.16,95.25 155.7,95.25 154.31,93.85 148.97,93.85 147.44,92.32 144.25,92.32 143.88,91.95 134.74,91.95 134.37,92.33 132.64,92.33 132.38,92.59 132.03,92.59 131.77,92.33 v2(129.92,92.33)
  LY4 w0.133: v2(161.74,95) 162.37,94.36 162.81,94.36 163.96,93.22 166.5,93.22 169.04,90.68 169.04,41.27 166.12,38.35 166.12,24.89 160.02,18.8 160.02,15.87 157.99,13.84 v2(157.99,12.19)
CLK8X_B: length 164.6
  TOP w0.127: RJ2.3 v2(96.14,137.67) ; RJ9.3 v2(41.91,89.28) ; v2(129.03,96.65) 129.16,96.52 R62.2
  LY3 w0.133: v2(129.54,132.46) 102.23,132.46 97.03,137.67 v2(96.14,137.67) 95,137.67 91.06,133.73 80.77,133.73 75.06,128.02 75.06,114.68 v2(73.03,112.65)
  LY4 w0.133: v2(129.03,96.65) 128.4,97.28 128.4,124.08 129.54,125.22 v2(129.54,132.46) ; v2(41.91,89.28) 42.93,90.3 42.93,104 48.91,109.98 70.36,109.98 v2(73.03,112.65)
CLK8X_B_10V5: length 127.5
  TOP w0.127: R61.2 129.54,94.74 v2(130.3,95.5) ; RJ15.1 v2(160.78,13.08)
  LY3 w0.133: v2(130.3,95.5) 133.1,92.71 134.87,92.71 135.37,92.21 143.4,92.21 143.89,92.71 147.32,92.71 148.84,94.23 154.05,94.23 155.45,95.63 v2(162.16,95.63)
  LY4 w0.133: v2(160.78,13.08) 160.78,18.92 166.5,24.64 166.5,38.23 169.29,41.02 169.29,41.16 169.3,41.17 169.3,91.05 166.75,93.6 164.19,93.6 v2(162.16,95.63)
CLK8X_B_PMIC: length 67.3
  TOP w0.127: v2(113.03,61.47) 113.03,64.01 113.66,64.64 113.66,69.21 115.57,71.12 v2(116.71,71.12) ; U32.14 81.03,58.38 80.52,58.89 v2(80.52,59.44)
  LY4 w0.133: v2(115.61,84.75) 115.61,82.75 116.08,82.28 116.08,78.49 116.71,77.85 v2(116.71,71.12) ; v2(113.03,61.47) 105.03,61.47 104.77,61.21 90.7,61.21 90.69,61.21 90.55,61.21 90.06,61.71 82.66,61.71 80.52,59.56 v2(80.52,59.44)
  BOTTOM w0.127: v2(80.52,59.44) 80.14,59.82 80.14,60.2 ; R63.2 115.44,84.92 v2(115.61,84.75)
CON_MMC1_CLK: length 7.1
  BOTTOM w0.127: P10.5 149.75,129.27 149.22,129.79 148.39,129.79 U67.3 147.97,129.38 146.27,129.38 146.18,129.29 145.29,129.29 144.91,129.67
CON_MMC1_CMD: length 6.8
  BOTTOM w0.127: 144.91,130.81 144.91,130.8 U67.5 147.19,130.8 147.85,131.47 P10.3
CON_MMC1_DAT0: length 8
  BOTTOM w0.127: P10.7 150.42,127.07 149.99,127.51 149.99,128.4 149.61,128.78 147.66,128.78 147.14,128.26 U66.5 144.91,128.26 144.91,128.27
CON_MMC1_DAT1: length 7.3
  BOTTOM w0.127: P10.8 150.51,125.97 149.22,127.26 U66.3 148.09,127.26 147.61,126.78 145.63,126.78 145.41,127 144.91,127
CON_MMC1_DAT2: length 6.8
  BOTTOM w0.127: P10.1 150.05,133.67 149.86,133.86 147.7,133.86 147.19,133.34 U68.5 144.91,133.34 144.91,133.35
CON_MMC1_DAT3: length 7
  BOTTOM w0.127: P10.2 149.59,132.57 149.36,132.34 U68.3 148.09,132.34 147.67,131.92 146.65,131.92 146.56,131.83 145.29,131.83 144.91,132.21
CONN_USB1_DM: length 22.7
  TOP w0.122: J1.2 132.23,160.98 132.23,161.87 129.11,165 124.23,165 122.98,163.75 122.98,160.47 124.82,158.63 124.82,155.37 124.56,155.12 FL2.2
CONN_USB1_DP: length 22.7
  TOP w0.122: J1.3 131.74,160.52 131.95,160.73 131.95,161.76 128.99,164.72 124.35,164.72 123.26,163.63 123.26,160.58 125.09,158.75 125.09,155.4 125.37,155.12 FL2.3
CONN_USB2_DM: length 5.6
  TOP w0.122: J2.2 155.3,158.73 154.46,157.89 154.46,156.26 154.71,156.01 FL1.3
CONN_USB2_DP: length 5.6
  TOP w0.122: J2.3 153.31,158.73 154.18,157.86 154.18,156.29 153.9,156.01 FL1.2
CONN_USB_D+: length 7.2
  TOP w0.13: J7.3 8,104.01 9.32,104.01 v4(9.52,103.81)
  BOTTOM w0.13: v4(9.52,103.81) 9.8,104.09 10.49,104.09 11.71,102.87 13.52,102.87 13.66,102.73 U52.14
CONN_USB_D-: length 7.2
  TOP w0.13: v4(9.52,104.67) 9.37,104.52 8.04,104.52 J7.2
  BOTTOM w0.13: U52.15 13.7,103.23 13.65,103.17 11.84,103.17 10.62,104.39 9.8,104.39 v4(9.52,104.67)
CONN_USB_RXN0: length 18.7
  TOP w0.122: FL5.3 130.96,152.07 130.7,152.34 130.7,153.29 131.22,153.81 131.22,154.31 131.33,154.42 U2.2 U2.9 131.33,156.48 131.22,156.59 131.22,156.96 130.54,157.63 127.62,157.63 126.9,158.36 126.9,160.67 127.62,161.39 128.54,161.39 129.01,160.92 129.01,159.36 128.66,159.02 J1.5
CONN_USB_RXP0: length 18.7
  TOP w0.122: FL5.2 130.15,152.07 130.42,152.34 130.42,153.4 130.94,153.92 130.94,154.31 130.83,154.42 U2.1 U2.10 130.83,156.48 130.94,156.59 130.94,156.85 130.43,157.35 127.51,157.35 126.62,158.24 126.62,160.78 127.51,161.67 128.65,161.67 129.29,161.04 129.29,159.43 J1.6
CONN_USB_TXN0: length 18.8
  TOP w0.122: J1.8 134.09,159.4 134.09,161.15 134.76,161.82 135.74,161.82 136.84,160.72 136.84,158.06 136.11,157.33 133.21,157.33 132.72,156.83 132.72,156.59 132.83,156.48 U2.6 U2.5 132.83,154.42 132.72,154.31 132.72,153.3 133.11,152.91 133.11,152.34 133.38,152.07 FL6.3
CONN_USB_TXP0: length 18.8
  TOP w0.122: J1.9 134.81,159.02 134.37,159.46 134.37,161.04 134.87,161.54 135.62,161.54 136.56,160.61 136.56,158.17 135.99,157.61 133.1,157.61 132.44,156.95 132.44,156.59 132.33,156.48 U2.7 U2.4 132.33,154.42 132.44,154.31 132.44,153.19 132.83,152.79 132.83,152.34 132.56,152.07 FL6.2
CS_P: length 24.5
  TOP w0.203: R38.2 v2(62.61,118.87)
  LY4 w0.305: v2(62.61,118.87) 63.12,119.38 64.01,119.38 64.77,120.14 64.77,121.54 63.75,122.55 60.45,122.55 55.5,127.51 55.5,129.79 54.48,130.81 53.97,130.81 53.59,131.19 v2(53.59,132.33)
  BOTTOM w0.305: C266.1 57.53,133.48 v2(56.77,132.72)
  vias: v2(51.43,132.72) v2(52.58,132.72) v2(55.63,132.72)
DET_USB1_VBUS: length 113.8
  TOP w0.102: 101.52,79.83 100.44,79.83 U27.F2
  TOP w0.127: U14.4 149.46,144.8 v2(149.48,144.78) ; v2(132.46,75.89) 129.34,75.89 128.91,76.33 128.14,76.33 127.89,76.07 121.92,76.07 121.41,75.56 116.46,75.56 116.06,75.96 105.7,75.96 101.82,79.83 101.52,79.83
  LY4 w0.133: v2(149.48,144.78) 149.48,140.72 130.81,122.05 130.81,100.84 131.06,100.58 131.06,96.39 131.44,96.01 131.44,95.12 132.84,93.73 132.84,90.8 131.95,89.92 131.95,79.5 132.46,78.99 v2(132.46,75.89)
DET_USB2_VBUS: length 113.8
  TOP w0.102: 101.52,80.48 100.44,80.48 U27.G2
  TOP w0.127: U13.4 v2(146.42,144.67) ; v2(130.18,76.71) 129.92,76.96 127.76,76.96 127.38,76.58 121.41,76.58 120.9,76.07 116.71,76.07 116.32,76.47 105.92,76.47 101.91,80.48 101.52,80.48
  LY4 w0.133: v2(130.18,76.71) 130.56,77.09 130.56,90.42 131.08,90.95 131.08,93.58 129.88,94.78 129.88,99.99 129.67,100.2 129.67,123.06 131.57,124.97 131.57,133.99 132.59,135 139.95,135 146.42,141.46 v2(146.42,144.67)
EMAC[1]_RXC: length 63.1
  TOP w0.127: U27.E11 v1(93.94,79.18) ; U40.27 v2(123.29,43.03)
  LY3 w0.133: v2(103.25,42.93) 103.93,42.93 104.09,43.08 104.09,43.28 104.24,43.43 104.46,43.43 104.62,43.28 104.62,43.08 104.78,42.93 114.05,42.93 114.67,42.3 117.74,42.3 118.24,42.8 123.07,42.8 v2(123.29,43.03)
  BOTTOM w0.127: v1(93.94,79.18) 94.61,78.51 94.61,75.31 96.06,73.87 96.06,69.68 97.79,67.94 97.79,60.07 98.55,59.31 98.55,58.29 97.79,57.53 97.79,52.83 101.6,49.02 101.6,47.27 102.49,46.38 102.49,43.69 v2(103.25,42.93)
EMAC[1]_RXCTL: length 64.8
  TOP w0.127: U40.15 120.89,36.95 v2(120.65,36.7) ; U27.F11 v1(93.94,79.83)
  LY3 w0.133: v1(93.94,79.83) 94.36,79.39 94.36,76.84 94.49,76.71 94.49,74.68 95.16,74 95.16,73.11 96.01,72.26 96.59,72.26 97.2,71.65 97.2,70.82 100.84,67.18 100.84,54.23 v2(101.47,53.59)
  BOTTOM w0.127: v2(101.47,53.59) 104.78,50.29 105.41,50.29 106.93,48.77 106.93,47.37 105.54,45.97 105.54,40 106.13,39.41 112.23,39.41 112.81,38.82 114.59,38.82 117.13,36.28 118.53,36.28 118.69,36.12 120.07,36.12 v2(120.65,36.7)
EMAC[1]_RXD0: length 64.1
  TOP w0.127: U27.D13 v1(93.29,78.53) ; U40.26 v2(124.05,41.88)
  LY3 w0.133: v2(124.05,41.88) 123.78,42.16 118.73,42.16 118.43,41.86 118.42,41.86 118.22,41.66 114.81,41.66 114.68,41.53 113.03,41.53 112.9,41.66 112.51,41.66 112.5,41.66 102.74,41.66 v2(101.98,42.42)
  BOTTOM w0.127: v1(93.29,78.53) 92.91,78.16 92.91,77.65 93.34,77.22 93.34,66.67 96.65,63.37 96.65,51.56 99.82,48.39 99.82,47.88 101.56,46.14 101.56,42.84 v2(101.98,42.42)
EMAC[1]_RXD1: length 64.7
  TOP w0.127: v2(124.97,41.91) 124.44,41.38 U40.25 ; U27.C13 v1(93.29,77.88)
  LY3 w0.133: v2(101.98,43.31) 102.87,42.42 104.27,42.42 104.44,42.59 113.88,42.59 114.43,42.04 118.24,42.04 118.32,42.12 118.32,42.12 118.74,42.54 123.18,42.54 123.18,42.54 124.33,42.54 v2(124.97,41.91)
  BOTTOM w0.127: v1(93.29,77.88) 93.67,77.51 93.67,66.86 97.03,63.5 97.03,51.69 100.2,48.51 100.2,48.01 101.98,46.23 v2(101.98,43.31)
EMAC[1]_RXD2: length 65.5
  TOP w0.127: U27.E13 v1(93.29,79.18) ; U40.24 v2(124.07,40.88)
  LY3 w0.133: v2(124.07,40.88) 117.34,40.88 117.22,40.77 112.01,40.77 111.38,41.4 v2(101.98,41.4)
  BOTTOM w0.127: v2(101.98,41.4) 101.31,42.08 101.31,45.82 99.44,47.69 99.44,48.18 96.27,51.35 96.27,63.25 93.09,66.42 93.09,66.57 93.09,66.57 93.09,76.28 93.09,76.28 93.09,76.96 92.68,77.37 92.68,78.58 v1(93.29,79.18)
EMAC[1]_RXD3: length 67.5
  TOP w0.102: U27.B13 93.29,77.24 93.29,76.17
  TOP w0.127: v2(102.74,40.89) 102.62,41.02 102.62,43.94 102.11,44.45 102.11,50.04 98.3,53.85 98.3,56.64 98.97,57.32 98.97,59.52 98.3,60.2 98.3,67.44 95.57,70.16 94.68,70.16 93.98,70.87 93.98,72.03 93.22,72.79 93.22,74.38 93.29,74.45 93.29,76.17 ; U40.23 124.46,40.39 v2(124.97,40.89)
  LY3 w0.133: v2(124.97,40.89) 124.54,40.46 124.24,40.46 124.24,40.46 123.27,40.46 122.56,39.75 118.36,39.75 117.6,38.99 116.62,38.99 116.5,39.12 115.44,39.12 114.68,39.88 108.2,39.88 107.19,40.89 v2(102.74,40.89)
EMAC[1]_TXC: length 44.3
  TOP w0.127: v2(103.63,47.01) 103.63,50.55 100.97,53.21 100.97,55.75 100.84,55.88 R101.1 ; U40.28 v2(122.39,44.58)
  LY3 w0.133: v2(122.39,44.58) 121.12,45.85 116.84,45.85 115.82,46.86 114.9,46.86 114.74,46.71 114.74,46.38 114.59,46.23 114.37,46.23 114.21,46.38 114.21,46.71 114.05,46.86 113.83,46.86 113.68,46.71 113.68,46.38 113.52,46.23 113.3,46.23 113.14,46.38 113.14,46.71 112.99,46.86 109.22,46.86 108.58,46.23 107.57,46.23 106.93,46.86 103.78,46.86 v2(103.63,47.01)
EMAC[1]_TXCTL: length 57.3
  TOP w0.127: U40.29 121.89,44.86 121.03,45.72 117.98,45.72 v2(117.35,46.35) ; U27.D11 v1(93.94,78.53)
  LY3 w0.133: v2(101.09,48.77) 102.74,48.77 104.26,47.25 116.45,47.25 v2(117.35,46.35)
  BOTTOM w0.127: v1(93.94,78.53) 94.33,78.15 94.33,76.16 94.18,76.01 94.18,71.05 97.54,67.69 97.54,52.32 v2(101.09,48.77)
EMAC[1]_TXD0: length 59.3
  TOP w0.127: v2(119.76,44.57) 119.76,43.94 119.9,43.81 U40.33 ; U27.A13 92.96,72.64 93.73,71.88 93.73,70.1 94.74,69.09 96.14,69.09 97.92,67.31 97.92,60.07 98.72,59.27 98.72,57.7 98.04,57.02 98.04,53.34 99.69,51.69 99.69,50.08 99.84,49.93 100.31,49.93 100.46,49.78 100.46,49.57 100.31,49.42 99.84,49.42 99.69,49.28 v2(99.69,46.48)
  LY3 w0.133: v2(119.76,44.57) 118.63,43.44 118.1,43.44 117.48,44.07 114.94,44.07 114.05,44.96 110.87,44.96 110.45,44.54 109.52,44.54 108.92,45.13 106,45.13 105.41,45.72 101.98,45.72 101.22,46.48 v2(99.69,46.48)
EMAC[1]_TXD1: length 58.6
  TOP w0.127: U27.A12 93.61,74.42 93.47,74.27 93.47,72.9 94.23,72.14 94.23,70.99 94.81,70.42 95.7,70.42 99.69,66.42 99.69,53.21 102.49,50.42 102.49,45.85 v2(103.25,45.08) ; U40.32 120.4,43.59 120.39,43.6 120.39,43.83 120.4,43.84 v2(120.4,44.07)
  LY3 w0.133: v2(103.25,45.08) 103.25,44.83 103.88,44.2 104.11,44.2 104.25,44.34 104.25,45.08 104.38,45.21 104.65,45.21 104.78,45.08 104.78,44.34 104.91,44.2 108.83,44.2 108.84,44.2 109.09,44.2 109.61,43.68 111.28,43.68 111.44,43.84 111.44,44.29 111.59,44.45 111.81,44.45 111.97,44.29 111.97,43.84 112.13,43.68 116.97,43.68 117.47,43.18 119.51,43.18 v2(120.4,44.07)
EMAC[1]_TXD2: length 58.7
  TOP w0.102: U27.B12 93.94,77.24 93.94,76.17
  TOP w0.127: v2(103.12,47.5) 103.12,50.42 99.95,53.59 99.95,66.68 95.95,70.67 95.32,70.67 95.12,70.87 95.12,71.63 93.73,73.02 93.73,74.17 93.94,74.38 93.94,76.17 ; v2(120.89,45.08) U40.31
  LY3 w0.133: v2(103.12,47.5) 103.12,46.86 103.51,46.48 106.68,46.48 107.31,45.85 109.64,45.85 109.79,46 109.79,46.33 109.95,46.48 110.17,46.48 110.33,46.33 110.33,46 110.48,45.85 110.7,45.85 110.86,46 110.86,46.33 111.02,46.48 111.24,46.48 111.39,46.33 111.39,46 111.55,45.85 111.77,45.85 111.93,46 111.93,46.33 112.08,46.48 112.3,46.48 112.46,46.33 112.46,46 112.62,45.85 115.57,45.85 116.46,44.96 117.35,44.96 117.9,45.51 120.48,45.51 120.89,45.1 v2(120.89,45.08)
EMAC[1]_TXD3: length 56.7
  TOP w0.127: U40.30 v2(121.39,44.32) ; U27.C11 v1(93.94,77.88)
  LY3 w0.133: v2(121.39,44.32) 120.9,44.32 120.14,45.08 119.25,45.08 118.75,44.58 116.2,44.58 115.32,45.47 107.06,45.47 106.42,46.11 102.86,46.11 v2(101.09,47.88)
  BOTTOM w0.127: v2(101.09,47.88) 100.58,48.39 100.58,48.64 97.28,51.94 97.28,63.88 93.92,67.24 93.92,76.28 93.94,76.3 v1(93.94,77.88)
EMU_RSTN: length 97.4
  TOP w0.127: v2(70.74,74.71) 70.74,74.68 69.6,73.53 69.6,69.47 69.98,69.09 69.98,64.77 69.6,64.39 69.6,63.75 68.07,62.23 68.07,53.21 70.1,51.18 70.1,46.86 71.63,45.34 71.63,42.8 72.26,42.16 91.44,42.16 v2(91.95,41.66) ; J14.6 v2(121.18,46.76)
  LY3 w0.133: v2(91.95,41.66) 94.87,41.66 99.06,45.85 99.06,47.75 101.22,49.91 108.58,49.91 109.47,49.02 118.87,49.02 121.13,46.76 v2(121.18,46.76)
  BOTTOM w0.127: R263.2 72.26,76.2 70.78,74.71 v2(70.74,74.71) ; v2(121.18,46.76) 121.28,46.86 R329.2
ENET_EN: length 73.8
  TOP w0.127: v1(98.49,81.78) 98.17,81.46 U27.H5 ; v2(116.71,39.5) 116.82,39.39 U40.7
  LY3 w0.133: v1(98.49,81.78) 99.12,81.15 100.2,81.15 101.71,79.65 104.12,79.65 106.43,77.34 113.16,77.34 114.05,78.23 117.73,78.23 119.42,76.54 v2(120.4,76.54)
  LY4 w0.133: v2(120.4,76.54) 124.29,72.64 126.24,72.64 129.02,69.86 129.02,55.36 120.65,46.99 120.65,46.35 119.25,44.96 119.25,43.05 116.71,40.51 v2(116.71,39.5)
  BOTTOM w0.127: R358.1 117.22,39.5 v2(116.71,39.5)
ENET_INH: length 81.4
  TOP w0.127: v2(124.08,38.99) 124.53,39.44 124.53,39.82 125.6,40.89 125.6,43.56 125.22,43.94 125.22,46.35 126.45,47.59 126.45,48.6 127,49.15 127,50.55 129.92,53.47 129.92,69.98 126.87,73.02 126.87,73.41 v2(126.24,74.04) ; U40.10 118.39,36.99 118.11,36.7 v2(117.47,36.7) ; v1(97.84,80.48) U27.G6
  LY3 w0.133: v1(97.84,80.48) 98.93,79.39 98.93,79.12 100.33,77.72 102.75,77.72 104.79,75.69 116.72,75.69 117.47,74.93 125.35,74.93 v2(126.24,74.04) ; v2(124.08,38.99) 121.16,36.07 118.1,36.07 v2(117.47,36.7)
  BOTTOM w0.127: v2(117.47,36.7) R365.1
ENET_INTSN: length 75.3
  TOP w0.127: U27.L4 v1(99.14,83.73)
  LY3 w0.133: v2(123.57,77.69) 121.88,79.38 121.15,79.38 121.14,79.38 120.39,79.38 118.36,81.41 114.05,81.41 113.54,80.9 106.05,80.9 104.97,81.97 102.05,81.97 100.67,83.35 99.52,83.35 v1(99.14,83.73)
  LY4 w0.133: v2(124.08,44.32) 124.08,45.59 126.36,47.88 126.36,49.4 129.54,52.58 129.54,73.02 127.51,75.06 126.2,75.06 v2(123.57,77.69)
  BOTTOM w0.127: v2(124.08,44.32) 123.27,44.32 122.39,43.43 117.86,43.43 117.6,43.69 R346.1 R342.1
ENET_WAKE: length 77.8
  TOP w0.127: v2(116.2,38.61) 116.48,38.89 U40.8 ; U27.G5 v1(98.49,80.48)
  LY3 w0.133: v2(127,74.17) 125.74,75.43 117.48,75.43 116.97,75.95 105.16,75.95 103,78.1 100.33,78.1 99.31,79.12 99.31,79.66 v1(98.49,80.48)
  LY4 w0.133: v2(127,74.17) 129.28,71.89 129.28,54.73 123.32,48.77 123.32,44.2 122.43,43.31 120.78,43.31 117.98,40.51 117.98,39.88 116.71,38.61 v2(116.2,38.61)
  BOTTOM w0.127: v2(116.2,38.61) R360.1
EXP_GPIO_INTR_43: length 82.3
  TOP w0.102: U27.E24 85.49,79.18 84.54,79.18 84.4,79.05
  TOP w0.127: 84.4,79.05 83.59,78.23 83.16,78.23 81.76,76.83 79.48,76.83 79.17,76.52 79.17,75.79 77.08,73.7 76.35,73.7 75.8,73.15 75.8,73.15 75.59,73.15 75.59,73.15 73.81,73.15 73.43,72.77 71.75,72.77 71.25,72.26 71.25,70.1 71.63,69.72 71.63,64.09 71.25,63.71 71.25,63.08 69.72,61.55 69.72,54.1 73.15,50.67 73.15,47.67 v2(73.11,47.62)
  LY3 w0.133: v2(73.11,47.62) 73.15,47.58 73.15,46.74 75.15,44.74 75.15,41.93 81.91,35.17 81.91,33.4 91.95,23.37 v2(91.95,20.07)
  BOTTOM w0.127: v2(91.95,20.07) 91.95,19.68 92.09,19.55 J19.43
EXP_GPIO_INTR_77: length 89.6
  TOP w0.127: v2(92.33,11.56) 92.33,11.81 R165.2 ; U27.E25 84.51,79.51 83.48,78.49 83.06,78.49 81.66,77.09 79.38,77.09 78.92,76.63 78.92,75.89 76.98,73.95 76.24,73.95 76.2,73.91 76.2,73.91 75.69,73.41 73.7,73.41 73.32,73.02 71.65,73.02 70.99,72.37 70.99,70 71.37,69.62 71.37,64.2 70.99,63.82 70.99,63.18 69.47,61.66 69.47,53.98 72.52,50.93 72.52,46.23 v2(73.15,45.59)
  LY3 w0.133: v2(92.33,11.56) 90.3,13.59 90.3,18.41 89.66,19.05 89.66,22.61 81.15,31.11 81.15,35.05 74.56,41.65 74.56,44.19 v2(73.15,45.59)
EXP_GPIO_OUT_57: length 74.4
  TOP w0.127: R184.2 99.82,17.65 99.31,18.16 v2(99.31,19.56) ; U27.D20 v1(88.09,78.53)
  LY3 w0.133: v1(88.09,78.53) 88.09,74.12 87.63,73.66 87.63,70.61 86.99,69.97 86.99,69.22 87.32,68.89 90.5,68.89 96.39,62.99 96.39,56.39 98.55,54.23 v2(99.23,54.23)
  BOTTOM w0.127: v2(99.31,19.56) 100.46,20.7 100.46,28.07 100.89,28.5 100.89,36.75 104.78,40.64 104.78,47.12 103.5,48.39 103.5,49.95 v2(99.23,54.23)
EXP_GPIO_OUT_74: length 78.4
  TOP w0.102: 88.09,76.17 88.09,77.88 U27.C20
  TOP w0.127: v2(89.28,30.48) 90.17,31.37 94.74,31.37 95.38,32 95.38,38.1 93.98,39.5 93.98,55.37 90.68,58.67 90.68,64.64 89.79,65.53 88.23,65.53 88.01,65.75 88.01,69.47 87.44,70.04 87.44,71.31 86.67,72.08 86.67,73.89 87.92,75.13 87.92,75.28 88.09,75.45 88.09,76.17
  LY3 w0.133: v2(94.48,14.48) 94.49,14.48 94.49,15.62 93.98,16.13 93.98,18.16 94.49,18.67 94.49,20.07 92.96,21.59 92.96,23.37 89.28,27.05 v2(89.28,30.48)
  BOTTOM w0.127: v2(94.48,14.48) J19.74
FB: length 7.5
  TOP w0.203: U19.11 55.23,112.15 55.63,111.76 v2(55.63,111.38) R49.2 ; v2(58.17,111.38) R43.1
  BOTTOM w0.203: v2(55.63,111.38) v2(58.17,111.38)
FB_5141: length 3.7
  TOP w0.203: R24.1 R26.2 75.95,127.51 77.24,126.21 U18.19
FPD_DOUT+: length 1.8
  TOP w0.112: 147.45,67.31 147.78,66.98 148.51,66.98 148.74,67.21 FL9.1
FPD_DOUT-: length 1.8
  TOP w0.112: FL9.4 148.74,66.4 148.51,66.62 147.78,66.62 147.45,66.29
GNSS_TIME_STAMP: length 28.8
  TOP w0.127: v2(154.81,102.36) 154.84,102.39 U21.51
  LY4 w0.133: v2(141.5,114.05) 143.76,114.05 144.65,114.94 154.31,114.94 154.69,114.55 154.69,104.8 154.81,104.67 v2(154.81,102.36)
  BOTTOM w0.127: RU2.10 v2(141.5,114.05)
H_CSI2_DX0: length 82.6
  TOP w0.102: U27.AC1 100.98,91.21
  TOP w0.112: v2(162.31,93.34) 161.9,92.94 160.54,92.94 160.43,93.05 160.43,93.23 160.32,93.34 160.1,93.34 159.98,93.23 159.98,93.05 158.76,91.82 156.34,91.82 156.06,91.54 154.58,91.54 149.63,96.49 149.1,96.49 148.78,96.17 148.78,95.46 148.67,95.35 148.44,95.35 148.33,95.46 148.33,96.17 148.01,96.49 147.49,96.49 147.17,96.17 147.17,95.46 147.06,95.35 146.84,95.35 146.73,95.46 146.73,96.17 146.41,96.49 145.89,96.49 145.57,96.17 145.57,95.46 145.46,95.35 145.23,95.35 145.12,95.46 145.12,96.17 144.8,96.49 144.28,96.49 143.96,96.17 143.96,95.46 143.85,95.35 143.63,95.35 143.52,95.46 143.52,96.17 143.2,96.49 142.68,96.49 142.36,96.17 142.36,95.46 142.25,95.35 142.02,95.35 141.91,95.46 141.91,96.17 141.59,96.49 141.06,96.49 140.74,96.17 140.74,95.72 140.62,95.61 140.4,95.61 140.29,95.72 140.29,96.17 139.97,96.49 139.44,96.49 139.12,96.17 139.12,95.59 139,95.48 138.78,95.48 138.67,95.59 138.67,96.17 138.35,96.49 135.79,96.49 133.22,99.06 116.59,99.06 109.83,92.3 103.1,92.3 102.03,91.24 101,91.24 100.98,91.21
  BOTTOM w0.112: P9.5 162.53,93.12 v2(162.31,93.34)
